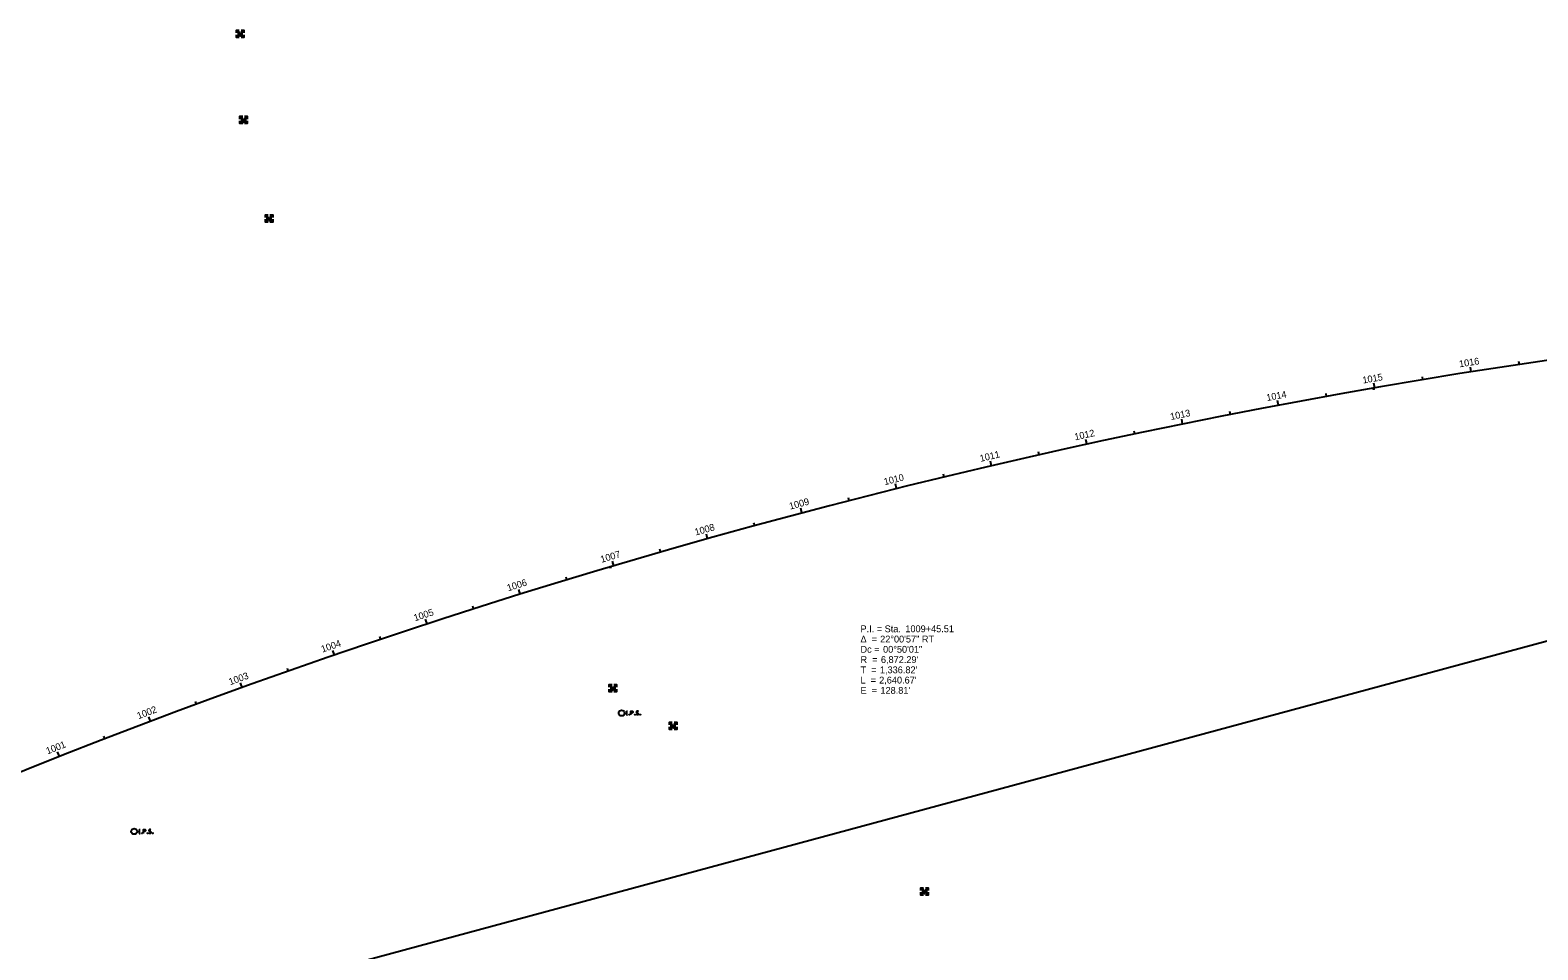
# Model space of a CAD drawing. Extents: x 2192033 to 2198234, y 657975 to 662607.
# Drawn here: x 2195140 to 2196682, y 661084 to 662025 of the extents above; entities that cross this region are included whole.
import ezdxf

# ---------------------------------------------------------------- set-up
doc = ezdxf.new("R2010")
doc.units = 0
for name, color, linetype in [('BR_P_Gen_Approach_Slab', 7, 'Continuous'), ('GE_X_Alignment_1000_Curve_Data', 7, 'Continuous'), ('GE_X_Alignment_1000_Stations', 7, 'Continuous'), ('GE_X_Alignment_100_Curve_Data', 7, 'Continuous'), ('GE_X_Alignment_100_Stations', 7, 'Continuous'), ('GE_X_Alignment_500_Curve_Data', 7, 'Continuous'), ('GE_X_Alignment_500_Stations', 7, 'Continuous'), ('RD_P_Text', 7, 'Continuous'), ('SH_Border', 7, 'Continuous'), ('SH_Data', 7, 'Continuous'), ('SH_Named_Boundary', 7, 'Continuous')]:
    doc.layers.add(name, color=color, linetype=linetype)

msp = doc.modelspace()

# ---------------------------------------------------------------- linework, layer by layer
at = {"layer": 'BR_P_Gen_Approach_Slab'}
for points in [[(2195750.1, 661328.5), (2195750.9, 661328.5)], [(2195750.1, 661324.5), (2195750.9, 661324.5)], [(2195750.5, 661324.5), (2195750.5, 661328.5)], [(2195752.9, 661325), (2195753, 661325), (2195753.1, 661325), (2195753.2, 661324.8), (2195753.2, 661324.7), (2195753.1, 661324.6), (2195753, 661324.5), (2195752.9, 661324.5), (2195752.8, 661324.6), (2195752.7, 661324.7), (2195752.7, 661324.8), (2195752.8, 661325), (2195752.9, 661325)], [(2195754.4, 661324.5), (2195754.4, 661328.5), (2195755.7, 661328.5), (2195755.9, 661328.5), (2195756.1, 661328.4), (2195756.2, 661328.3), (2195756.2, 661328.3), (2195756.4, 661328.1), (2195756.4, 661328), (2195756.5, 661327.7), (2195756.5, 661327.3), (2195756.5, 661327.2), (2195756.4, 661327), (2195756.3, 661326.8), (2195756.2, 661326.7), (2195756.1, 661326.6), (2195756, 661326.6), (2195755.7, 661326.5), (2195754.4, 661326.5)], [(2195758.5, 661325), (2195758.7, 661325), (2195758.7, 661325), (2195758.8, 661324.8), (2195758.8, 661324.7), (2195758.7, 661324.6), (2195758.7, 661324.5), (2195758.5, 661324.5), (2195758.4, 661324.6), (2195758.4, 661324.7), (2195758.4, 661324.8), (2195758.4, 661325), (2195758.5, 661325)], [(2195761.9, 661328.2), (2195761.9, 661328.3), (2195761.8, 661328.3), (2195761.6, 661328.4), (2195761.3, 661328.5), (2195761, 661328.5), (2195761, 661328.5), (2195760.6, 661328.4), (2195760.3, 661328.2), (2195760.1, 661328), (2195760, 661327.7), (2195760, 661327.5), (2195760.1, 661327.3), (2195760.3, 661327.1), (2195761.8, 661326.1), (2195762, 661326), (2195762, 661325.9), (2195762.1, 661325.7), (2195762.1, 661325.5), (2195762.1, 661325.3), (2195762, 661325.2), (2195762, 661325), (2195761.9, 661324.9), (2195761.9, 661324.8), (2195761.8, 661324.7), (2195761.7, 661324.6), (2195761.6, 661324.6), (2195761.5, 661324.5), (2195761.3, 661324.5), (2195760.9, 661324.5), (2195760.6, 661324.6), (2195760.3, 661324.8), (2195760, 661325)], [(2195764, 661325), (2195764.1, 661325), (2195764.2, 661325), (2195764.3, 661324.8), (2195764.3, 661324.7), (2195764.2, 661324.6), (2195764.1, 661324.5), (2195764, 661324.5), (2195763.9, 661324.6), (2195763.8, 661324.7), (2195763.8, 661324.8), (2195763.9, 661325), (2195764, 661325)], [(2195251.4, 661207.4), (2195252.3, 661207.4)], [(2195251.4, 661203.4), (2195252.3, 661203.4)], [(2195251.8, 661203.4), (2195251.8, 661207.4)], [(2195254.2, 661203.9), (2195254.4, 661203.9), (2195254.4, 661203.8), (2195254.5, 661203.7), (2195254.5, 661203.5), (2195254.4, 661203.4), (2195254.4, 661203.4), (2195254.2, 661203.4), (2195254.1, 661203.4), (2195254, 661203.5), (2195254, 661203.7), (2195254.1, 661203.8), (2195254.2, 661203.9)], [(2195255.7, 661203.4), (2195255.7, 661207.4), (2195257.1, 661207.4), (2195257.2, 661207.3), (2195257.4, 661207.3), (2195257.5, 661207.2), (2195257.5, 661207.1), (2195257.7, 661207), (2195257.7, 661206.8), (2195257.8, 661206.6), (2195257.8, 661206.2), (2195257.8, 661206.1), (2195257.7, 661205.9), (2195257.6, 661205.7), (2195257.5, 661205.6), (2195257.4, 661205.5), (2195257.3, 661205.4), (2195257.1, 661205.4), (2195255.7, 661205.4)], [(2195259.8, 661203.9), (2195260, 661203.9), (2195260.1, 661203.8), (2195260.1, 661203.7), (2195260.1, 661203.5), (2195260.1, 661203.4), (2195260, 661203.4), (2195259.8, 661203.4), (2195259.8, 661203.4), (2195259.7, 661203.5), (2195259.7, 661203.7), (2195259.8, 661203.8), (2195259.8, 661203.9)], [(2195263.3, 661207.1), (2195263.2, 661207.1), (2195263.1, 661207.2), (2195262.9, 661207.3), (2195262.6, 661207.4), (2195262.3, 661207.4), (2195262.3, 661207.4), (2195261.9, 661207.3), (2195261.6, 661207.1), (2195261.4, 661206.8), (2195261.4, 661206.6), (2195261.4, 661206.4), (2195261.4, 661206.1), (2195261.6, 661205.9), (2195263.1, 661205), (2195263.3, 661204.8), (2195263.3, 661204.7), (2195263.4, 661204.5), (2195263.4, 661204.3), (2195263.4, 661204.1), (2195263.3, 661204), (2195263.3, 661203.9), (2195263.2, 661203.7), (2195263.2, 661203.6), (2195263.1, 661203.5), (2195263, 661203.5), (2195262.9, 661203.4), (2195262.8, 661203.4), (2195262.6, 661203.4), (2195262.2, 661203.4), (2195261.9, 661203.4), (2195261.6, 661203.6), (2195261.4, 661203.8)], [(2195265.3, 661203.9), (2195265.4, 661203.9), (2195265.5, 661203.8), (2195265.6, 661203.7), (2195265.6, 661203.5), (2195265.5, 661203.4), (2195265.4, 661203.4), (2195265.3, 661203.4), (2195265.2, 661203.4), (2195265.1, 661203.5), (2195265.1, 661203.7), (2195265.2, 661203.8), (2195265.3, 661203.9)]]:
    msp.add_lwpolyline(points, dxfattribs=at)
for centre in [(2195745, 661326.5), (2195246.3, 661205.4)]:
    msp.add_circle(centre, 3, dxfattribs=at)
at = {"layer": 'GE_X_Alignment_1000_Stations'}
for p, q in [((2196515.5, 661659.2), (2196515, 661662.2)), ((2196026.4, 661556.1), (2196025.2, 661561)), ((2195546, 661417.7), (2195545.1, 661420.5))]:
    msp.add_line(p, q, dxfattribs=at)
at = {"layer": 'GE_X_Alignment_100_Stations'}
for p, q in [((2196614.2, 661675.6), (2196613.4, 661680.5)), ((2196663.6, 661683.2), (2196663.1, 661686.2)), ((2196515.5, 661659.2), (2196514.7, 661664.2)), ((2196564.8, 661667.6), (2196564.3, 661670.5)), ((2196417.1, 661641.5), (2196416.2, 661646.4)), ((2196466.3, 661650.5), (2196465.7, 661653.5)), ((2196368, 661632), (2196367.4, 661635)), ((2196319, 661622.3), (2196318, 661627.2)), ((2196221.1, 661601.6), (2196220, 661606.5)), ((2196270, 661612.1), (2196269.4, 661615.1)), ((2196123.6, 661579.6), (2196122.4, 661584.4)), ((2196172.3, 661590.8), (2196171.6, 661593.7)), ((2196074.9, 661568), (2196074.2, 661570.9)), ((2196026.4, 661556.1), (2196025.2, 661561)), ((2195977.9, 661543.8), (2195977.2, 661546.7)), ((2195929.5, 661531.2), (2195928.2, 661536.1)), ((2195833, 661504.9), (2195831.7, 661509.7)), ((2195881.2, 661518.3), (2195880.4, 661521.1)), ((2195784.9, 661491.3), (2195784.1, 661494.1)), ((2195736.9, 661477.2), (2195735.5, 661482)), ((2195689.1, 661462.9), (2195688.2, 661465.7)), ((2195641.3, 661448.2), (2195639.8, 661452.9)), ((2195593.6, 661433.1), (2195592.7, 661436)), ((2195546, 661417.7), (2195544.5, 661422.4)), ((2195498.6, 661401.9), (2195497.6, 661404.8)), ((2195451.2, 661385.8), (2195449.6, 661390.6)), ((2195404, 661369.4), (2195403, 661372.2)), ((2195356.9, 661352.6), (2195355.2, 661357.3)), ((2195309.9, 661335.5), (2195308.9, 661338.3)), ((2195263.1, 661318), (2195261.3, 661322.7)), ((2195216.4, 661300.2), (2195215.3, 661303)), ((2195169.8, 661282), (2195168, 661286.7))]:
    msp.add_line(p, q, dxfattribs=at)
at = {"layer": 'GE_X_Alignment_500_Stations'}
for p, q in [((2196614.2, 661675.6), (2196613.7, 661678.5)), ((2196515.5, 661659.2), (2196514.7, 661664.2)), ((2196417.1, 661641.5), (2196416.5, 661644.4)), ((2196319, 661622.3), (2196318.4, 661625.2)), ((2196221.1, 661601.6), (2196220.5, 661604.6)), ((2196123.6, 661579.6), (2196122.9, 661582.5)), ((2196026.4, 661556.1), (2196025.2, 661561)), ((2195929.5, 661531.2), (2195928.8, 661534.1)), ((2195833, 661504.9), (2195832.2, 661507.8)), ((2195736.9, 661477.2), (2195736.1, 661480.1)), ((2195641.3, 661448.2), (2195640.4, 661451)), ((2195546, 661417.7), (2195544.5, 661422.4)), ((2195451.2, 661385.8), (2195450.3, 661388.7)), ((2195356.9, 661352.6), (2195355.9, 661355.4)), ((2195263.1, 661318), (2195262, 661320.8)), ((2195169.8, 661282), (2195168.7, 661284.8))]:
    msp.add_line(p, q, dxfattribs=at)
at = {"layer": 'RD_P_Text'}
msp.add_arc((2197687.9, 654887.7), 6872.3, 93.57492, 115.59076, dxfattribs=at)
at = {"layer": 'SH_Border'}
msp.add_line((2192833.4, 660357.6), (2197996.1, 661752.8), dxfattribs=at)
at = {"layer": 'SH_Data'}
for p, q in [((2196513.2, 661658.7), (2196515.7, 661658.7)), ((2196514.4, 661659.9), (2196514.4, 661657.4)), ((2196514.4, 661658.7), (2196514.4, 661658.7)), ((2195733.5, 661477.2), (2195733.5, 661474.7)), ((2195732.2, 661475.9), (2195734.7, 661475.9)), ((2195733.5, 661475.9), (2195733.5, 661475.9))]:
    msp.add_line(p, q, dxfattribs=at)
at = {"layer": 'SH_Named_Boundary'}
for p, q in [((2195354.8, 662021.5), (2195354.8, 662021.5)), ((2195358.3, 661933.3), (2195358.3, 661933.3)), ((2195384.4, 661832.6), (2195384.4, 661832.6)), ((2195736.1, 661352), (2195736.1, 661352)), ((2195797.7, 661313.4), (2195797.7, 661313.4)), ((2196054.9, 661144.1), (2196054.9, 661144.1))]:
    msp.add_line(p, q, dxfattribs=at)
for points in [[(2195351, 662022.5), (2195351, 662025.3), (2195353.8, 662025.3)], [(2195353.8, 662017.8), (2195351, 662017.8), (2195351, 662020.6)], [(2195352.9, 662019), (2195352.9, 662024), (2195354.8, 662019), (2195356.6, 662024), (2195356.6, 662019)], [(2195355.7, 662025.3), (2195358.5, 662025.3), (2195358.5, 662022.5)], [(2195358.5, 662020.6), (2195358.5, 662017.8), (2195355.7, 662017.8)], [(2195354.5, 661934.3), (2195354.5, 661937.1), (2195357.3, 661937.1)], [(2195357.3, 661929.6), (2195354.5, 661929.6), (2195354.5, 661932.4)], [(2195356.4, 661930.8), (2195356.4, 661935.8), (2195358.3, 661930.8), (2195360.1, 661935.8), (2195360.1, 661930.8)], [(2195359.1, 661937.1), (2195362, 661937.1), (2195362, 661934.3)], [(2195362, 661932.4), (2195362, 661929.6), (2195359.1, 661929.6)], [(2195380.6, 661833.6), (2195380.6, 661836.4), (2195383.4, 661836.4)], [(2195383.4, 661828.9), (2195380.6, 661828.9), (2195380.6, 661831.7)], [(2195382.5, 661830.1), (2195382.5, 661835.1), (2195384.4, 661830.1), (2195386.2, 661835.1), (2195386.2, 661830.1)], [(2195385.2, 661836.4), (2195388.1, 661836.4), (2195388.1, 661833.6)], [(2195388.1, 661831.7), (2195388.1, 661828.9), (2195385.2, 661828.9)], [(2195732.4, 661353), (2195732.4, 661355.8), (2195735.2, 661355.8)], [(2195734.3, 661349.5), (2195734.3, 661354.5), (2195736.1, 661349.5), (2195738, 661354.5), (2195738, 661349.5)], [(2195737, 661355.8), (2195739.9, 661355.8), (2195739.9, 661353)], [(2195735.2, 661348.3), (2195732.4, 661348.3), (2195732.4, 661351.1)], [(2195739.9, 661351.1), (2195739.9, 661348.3), (2195737, 661348.3)], [(2195793.9, 661314.4), (2195793.9, 661317.2), (2195796.7, 661317.2)], [(2195796.7, 661309.7), (2195793.9, 661309.7), (2195793.9, 661312.5)], [(2195795.8, 661310.9), (2195795.8, 661315.9), (2195797.7, 661310.9), (2195799.5, 661315.9), (2195799.5, 661310.9)], [(2195798.6, 661317.2), (2195801.4, 661317.2), (2195801.4, 661314.4)], [(2195801.4, 661312.5), (2195801.4, 661309.7), (2195798.6, 661309.7)], [(2196051.2, 661145), (2196051.2, 661147.8), (2196054, 661147.8)], [(2196054, 661140.3), (2196051.2, 661140.3), (2196051.2, 661143.1)], [(2196053.1, 661141.6), (2196053.1, 661146.6), (2196054.9, 661141.6), (2196056.8, 661146.6), (2196056.8, 661141.6)], [(2196055.8, 661147.8), (2196058.7, 661147.8), (2196058.7, 661145)], [(2196058.7, 661143.1), (2196058.7, 661140.3), (2196055.8, 661140.3)]]:
    msp.add_lwpolyline(points, dxfattribs=at)

# ---------------------------------------------------------------- texts
at = {"layer": 'GE_X_Alignment_1000_Curve_Data'}
for s, p in [('P.I. = Sta. ', (2195989.4, 661409.2)), ('1009+45.51', (2196035.3, 661409.2)), ('Δ  = ', (2195989.4, 661398.7)), ('22°00\'57" RT', (2196009.5, 661398.7)), ('Dc = ', (2195989.4, 661388.2)), ('R  = ', (2195989.4, 661377.7)), ("6,872.29'", (2196010.3, 661377.7)), ('00°50\'01"', (2196012.5, 661388.2)), ('T  = ', (2195989.4, 661367.2)), ("1,336.82'", (2196009.3, 661367.2)), ('L  = ', (2195989.4, 661356.7)), ('E  = ', (2195989.4, 661346.2)), ("2,640.67'", (2196008.5, 661356.7)), ("128.81'", (2196009.8, 661346.2))]:
    msp.add_text(s, height=7, dxfattribs=at).set_placement(p)
at = {"layer": 'GE_X_Alignment_1000_Stations'}
msp.add_text('1010', height=7, rotation=13.991, dxfattribs=at).set_placement((2196014.2, 661559.6))
at = {"layer": 'GE_X_Alignment_100_Curve_Data'}
for s, p in [('P.I. = Sta. ', (2195989.4, 661409.2)), ('1009+45.51', (2196035.3, 661409.2)), ('Δ  = ', (2195989.4, 661398.7)), ('22°00\'57" RT', (2196009.5, 661398.7)), ('Dc = ', (2195989.4, 661388.2)), ('R  = ', (2195989.4, 661377.7)), ("6,872.29'", (2196010.3, 661377.7)), ('00°50\'01"', (2196012.5, 661388.2)), ('T  = ', (2195989.4, 661367.2)), ("1,336.82'", (2196009.3, 661367.2)), ('L  = ', (2195989.4, 661356.7)), ('E  = ', (2195989.4, 661346.2)), ("2,640.67'", (2196008.5, 661356.7)), ("128.81'", (2196009.8, 661346.2))]:
    msp.add_text(s, height=7, dxfattribs=at).set_placement(p)
at = {"layer": 'GE_X_Alignment_100_Stations'}
for s, rotation, p in [('1016', 8.9887, (2196602.4, 661680.2)), ('1015', 9.8224, (2196503.6, 661663.6)), ('1014', 10.6562, (2196405.3, 661645.7)), ('1013', 11.4899, (2196307, 661626.3)), ('1012', 12.3236, (2196209.1, 661605.5)), ('1011', 13.1573, (2196112.3, 661583.5)), ('1010', 13.991, (2196014.2, 661559.6)), ('1009', 14.8248, (2195917.4, 661534.6)), ('1008', 15.6585, (2195820.8, 661508.1)), ('1007', 16.4922, (2195724.5, 661480.2)), ('1006', 17.3259, (2195628.9, 661451)), ('1005', 18.1597, (2195533.6, 661420.3)), ('1004', 18.9934, (2195438.9, 661388.3)), ('1003', 19.8271, (2195344.5, 661354.9)), ('1002', 20.6608, (2195250.7, 661320.1)), ('1001', 21.4945, (2195157.7, 661284.1))]:
    msp.add_text(s, height=7, rotation=rotation, dxfattribs=at).set_placement(p)
at = {"layer": 'GE_X_Alignment_500_Curve_Data'}
for s, p in [('P.I. = Sta. ', (2195989.4, 661409.2)), ('1009+45.51', (2196035.3, 661409.2)), ('Δ  = ', (2195989.4, 661398.7)), ('22°00\'57" RT', (2196009.5, 661398.7)), ('Dc = ', (2195989.4, 661388.2)), ('R  = ', (2195989.4, 661377.7)), ("6,872.29'", (2196010.3, 661377.7)), ('00°50\'01"', (2196012.5, 661388.2)), ('T  = ', (2195989.4, 661367.2)), ("1,336.82'", (2196009.3, 661367.2)), ('L  = ', (2195989.4, 661356.7)), ('E  = ', (2195989.4, 661346.2)), ("2,640.67'", (2196008.5, 661356.7)), ("128.81'", (2196009.8, 661346.2))]:
    msp.add_text(s, height=7, dxfattribs=at).set_placement(p)
at = {"layer": 'GE_X_Alignment_500_Stations'}
for s, rotation, p in [('1015', 9.8224, (2196503.6, 661663.6)), ('1010', 13.991, (2196014.2, 661559.6)), ('1005', 18.1597, (2195533.6, 661420.3))]:
    msp.add_text(s, height=7, rotation=rotation, dxfattribs=at).set_placement(p)

doc.saveas('drawing.dxf')
